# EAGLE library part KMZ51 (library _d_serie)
Magnetic Field Sensor
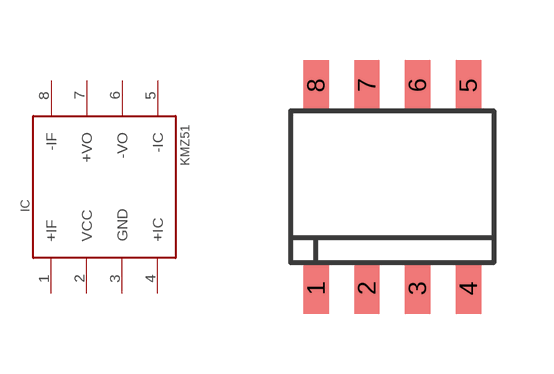
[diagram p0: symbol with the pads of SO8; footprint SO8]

Designator prefix IC

## KMZ51  [SO8]
1  +IF
2  VCC  pwr
3  GND  pwr
4  +IC
5  -IC
6  -VO
7  +VO
8  -IF

## Footprint SO8 (pad centres in mm)
SO8: plastic small outline package; 8 leads; body width 3.9 mm
smd 0.635 x 1.27: 1 -1.905,-2.54; 2 -0.635,-2.54; 3 0.635,-2.54; 4 1.905,-2.54; 5 1.905,2.54; 6 0.635,2.54; 7 -0.635,2.54; 8 -1.905,2.54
